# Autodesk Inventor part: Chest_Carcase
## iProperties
Created: 2006-01
Part Number: Chest_Carcase
Document SubType Name: Modeling
Designer: Martin
Author: Martin
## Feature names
1. Extrusion1
2. Shell1
3. Hole1
4. Extrusion2
5. Rectangular Pattern1
